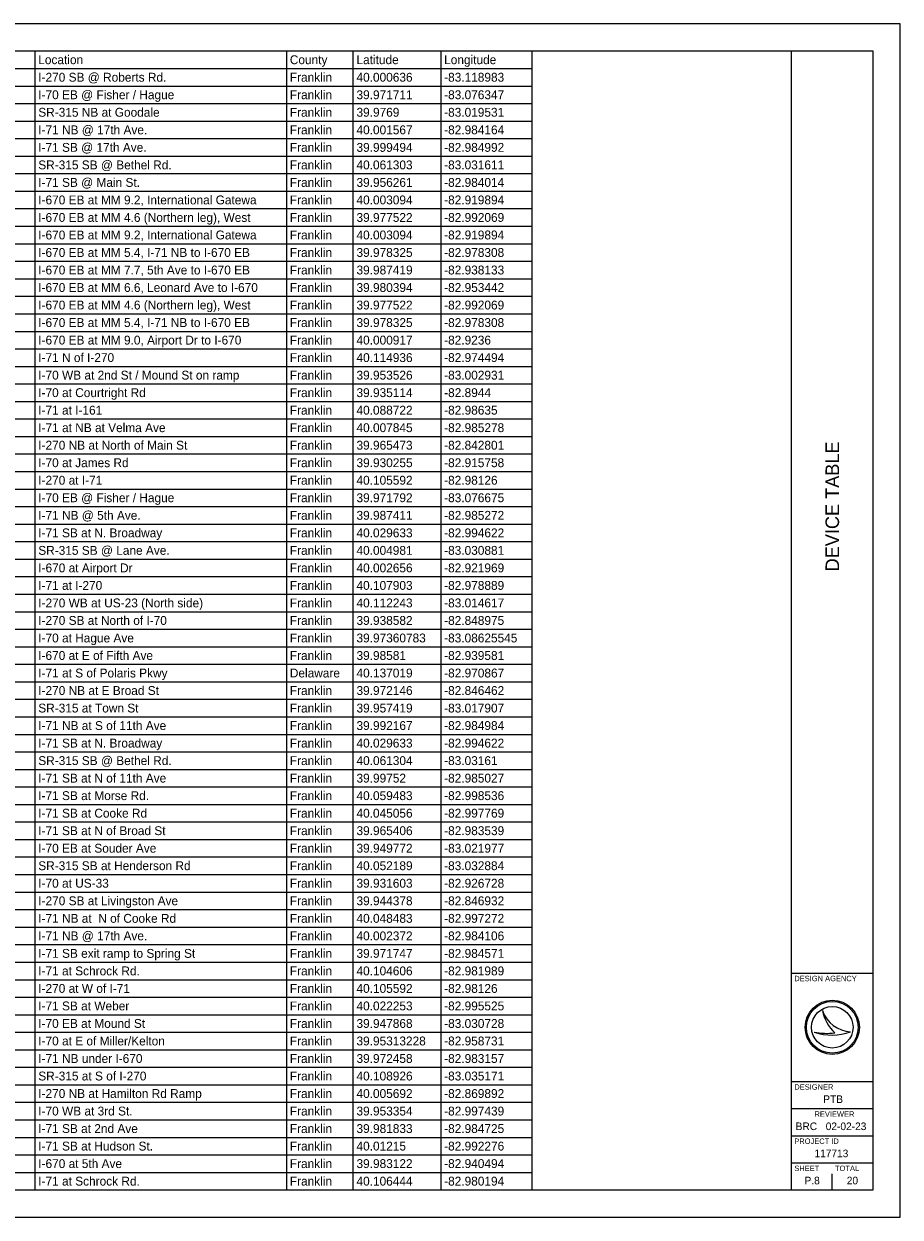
# Model space of a CAD drawing. Extents: x 0 to 34, y 0 to 22.
# Drawn here: x 17.86 to 34, y 0 to 22 of the extents above; entities that cross this region are included whole.
import ezdxf

# ---------------------------------------------------------------- set-up
doc = ezdxf.new("R2010")
doc.units = 0
for name, color, linetype in [('SH_Border', 7, 'Continuous'), ('SH_Cut_Line', 7, 'Continuous'), ('SH_Data', 7, 'Continuous'), ('SH_Text', 7, 'Continuous')]:
    doc.layers.add(name, color=color, linetype=linetype)

msp = doc.modelspace()

# ---------------------------------------------------------------- linework, layer by layer
at = {"layer": 'SH_Border'}
for p, q in [((32, 0.5), (32, 21.5)), ((32, 4.5), (33.5, 4.5)), ((32, 2.5), (33.5, 2.5)), ((32, 2), (33.5, 2)), ((32, 1.5), (33.5, 1.5)), ((32, 1), (33.5, 1))]:
    msp.add_line(p, q, dxfattribs=at)
msp.add_lwpolyline([(1.5, 21.5), (33.5, 21.5), (33.5, 0.5), (1.5, 0.5)], close=True, dxfattribs=at)
at = {"layer": 'SH_Cut_Line'}
msp.add_lwpolyline([(0, 0), (34, 0), (34, 22), (0, 22)], close=True, dxfattribs=at)
at = {"layer": 'SH_Data'}
for p, q in [((32.567, 3.81), (32.567, 3.81)), ((32.417, 3.41), (32.417, 3.41)), ((32.75, 3.5), (32.75, 3.5)), ((33.087, 3.419), (33.087, 3.419)), ((32.375, 0.675), (32.375, 0.675)), ((32.75, 0.5), (32.75, 0.8))]:
    msp.add_line(p, q, dxfattribs=at)
for radius in [0.5, 0.477, 0.477, 0.382]:
    msp.add_circle((32.75, 3.5), radius, dxfattribs=at)
for centre, radius, start, end in [((33.116, 3.998), 0.58, 198.9257, 198.9319), ((33.347, 3.97), 0.796, 191.6379, 191.6421), ((33.116, 3.998), 0.58, 198.9319, 267.1657), ((33.347, 3.97), 0.796, 191.6421, 226.0947), ((32.739, 4.37), 1.013, 251.4576, 290.0832), ((32.648, 4.654), 1.266, 259.4964, 259.4995), ((32.739, 4.37), 1.013, 251.4527, 251.4576), ((32.648, 4.654), 1.266, 259.4995, 276.6672)]:
    msp.add_arc(centre, radius, start, end, dxfattribs=at)
at = {"layer": 'SH_Text'}
for p, q in [((1.5, 21.5), (27.214, 21.5)), ((18.056, 21.5), (18.056, 0.502)), ((22.692, 21.5), (22.692, 0.502)), ((23.919, 21.5), (23.919, 0.502)), ((25.535, 21.5), (25.535, 0.502)), ((27.214, 21.5), (27.214, 0.502)), ((1.5, 21.177), (27.214, 21.177)), ((1.5, 20.854), (27.214, 20.854)), ((1.5, 20.531), (27.214, 20.531)), ((1.5, 20.208), (27.214, 20.208)), ((1.5, 19.885), (27.214, 19.885)), ((1.5, 19.562), (27.214, 19.562)), ((1.5, 19.239), (27.214, 19.239)), ((1.5, 18.916), (27.214, 18.916)), ((1.5, 18.593), (27.214, 18.593)), ((1.5, 18.269), (27.214, 18.269)), ((1.5, 17.946), (27.214, 17.946)), ((1.5, 17.623), (27.214, 17.623)), ((1.5, 17.3), (27.214, 17.3)), ((1.5, 16.977), (27.214, 16.977)), ((1.5, 16.654), (27.214, 16.654)), ((1.5, 16.331), (27.214, 16.331)), ((1.5, 16.008), (27.214, 16.008)), ((1.5, 15.685), (27.214, 15.685)), ((1.5, 15.362), (27.214, 15.362)), ((1.5, 15.039), (27.214, 15.039)), ((1.5, 14.716), (27.214, 14.716)), ((1.5, 14.393), (27.214, 14.393)), ((1.5, 14.07), (27.214, 14.07)), ((1.5, 13.747), (27.214, 13.747)), ((1.5, 13.424), (27.214, 13.424)), ((1.5, 13.101), (27.214, 13.101)), ((1.5, 12.778), (27.214, 12.778)), ((1.5, 12.455), (27.214, 12.455)), ((1.5, 12.132), (27.214, 12.132)), ((1.5, 11.809), (27.214, 11.809)), ((1.5, 11.486), (27.214, 11.486)), ((1.5, 11.162), (27.214, 11.162)), ((1.5, 10.839), (27.214, 10.839)), ((1.5, 10.516), (27.214, 10.516)), ((1.5, 10.193), (27.214, 10.193)), ((1.5, 9.87), (27.214, 9.87)), ((1.5, 9.547), (27.214, 9.547)), ((1.5, 9.224), (27.214, 9.224)), ((1.5, 8.901), (27.214, 8.901)), ((1.5, 8.578), (27.214, 8.578)), ((1.5, 8.255), (27.214, 8.255)), ((1.5, 7.932), (27.214, 7.932)), ((1.5, 7.609), (27.214, 7.609)), ((1.5, 7.286), (27.214, 7.286)), ((1.5, 6.963), (27.214, 6.963)), ((1.5, 6.64), (27.214, 6.64)), ((1.5, 6.317), (27.214, 6.317)), ((1.5, 5.994), (27.214, 5.994)), ((1.5, 5.671), (27.214, 5.671)), ((1.5, 5.348), (27.214, 5.348)), ((1.5, 5.025), (27.214, 5.025)), ((1.5, 4.702), (27.214, 4.702)), ((1.5, 4.378), (27.214, 4.378)), ((1.5, 4.055), (27.214, 4.055)), ((1.5, 3.732), (27.214, 3.732)), ((1.5, 3.409), (27.214, 3.409)), ((1.5, 3.086), (27.214, 3.086)), ((1.5, 2.763), (27.214, 2.763)), ((1.5, 2.44), (27.214, 2.44)), ((1.5, 2.117), (27.214, 2.117)), ((1.5, 1.794), (27.214, 1.794)), ((1.5, 1.471), (27.214, 1.471)), ((1.5, 1.148), (27.214, 1.148)), ((1.5, 0.825), (27.214, 0.825)), ((1.5, 0.502), (27.214, 0.502))]:
    msp.add_line(p, q, dxfattribs=at)

# ---------------------------------------------------------------- texts
at = {"layer": 'SH_Data'}
msp.add_text('DEVICE TABLE', height=0.25, rotation=90, dxfattribs=at).set_placement((32.875, 11.905))
for s, height, p in [('DESIGN AGENCY', 0.1, (32.05, 4.35)), ('DESIGNER', 0.1, (32.05, 2.35)), ('PTB', 0.14, (32.584, 2.105)), ('REVIEWER', 0.1, (32.422, 1.85)), ('BRC', 0.14, (32.075, 1.605)), ('02-02-23', 0.14, (32.629, 1.605)), ('PROJECT ID', 0.1, (32.05, 1.35)), ('117713', 0.14, (32.421, 1.105)), ('SHEET', 0.1, (32.05, 0.85)), ('TOTAL', 0.1, (32.8, 0.85)), ('P.8', 0.14, (32.239, 0.605)), ('20', 0.14, (33.017, 0.605))]:
    msp.add_text(s, height=height, dxfattribs=at).set_placement(p)
at = {"layer": 'SH_Text'}
for s, height, p in [('Location', 0.1635, (18.121, 21.257)), ('County', 0.1635, (22.756, 21.257)), ('Latitude', 0.1635, (23.984, 21.257)), ('Longitude', 0.1635, (25.599, 21.257)), ('I-270 SB @ Roberts Rd.', 0.16346, (18.121, 20.934)), ('Franklin', 0.1635, (22.756, 20.934)), ('40.000636', 0.1635, (23.984, 20.934)), ('-83.118983', 0.1635, (25.599, 20.934)), ('I-70 EB @ Fisher / Hague', 0.16346, (18.121, 20.611)), ('Franklin', 0.1635, (22.756, 20.611)), ('39.971711', 0.1635, (23.984, 20.611)), ('-83.076347', 0.1635, (25.599, 20.611)), ('SR-315 NB at Goodale', 0.16346, (18.121, 20.288)), ('Franklin', 0.1635, (22.756, 20.288)), ('39.9769', 0.1635, (23.984, 20.288)), ('-83.019531', 0.1635, (25.599, 20.288)), ('I-71 NB @ 17th Ave.', 0.16346, (18.121, 19.964)), ('Franklin', 0.1635, (22.756, 19.964)), ('40.001567', 0.1635, (23.984, 19.964)), ('-82.984164', 0.1635, (25.599, 19.964)), ('I-71 SB @ 17th Ave.', 0.16346, (18.121, 19.641)), ('Franklin', 0.1635, (22.756, 19.641)), ('39.999494', 0.1635, (23.984, 19.641)), ('-82.984992', 0.1635, (25.599, 19.641)), ('SR-315 SB @ Bethel Rd.', 0.16346, (18.121, 19.318)), ('Franklin', 0.1635, (22.756, 19.318)), ('40.061303', 0.1635, (23.984, 19.318)), ('-83.031611', 0.1635, (25.599, 19.318)), ('I-71 SB @ Main St.', 0.16346, (18.121, 18.995)), ('Franklin', 0.1635, (22.756, 18.995)), ('39.956261', 0.1635, (23.984, 18.995)), ('-82.984014', 0.1635, (25.599, 18.995)), ('I-670 EB at MM 9.2, International Gatewa', 0.16346, (18.121, 18.672)), ('Franklin', 0.1635, (22.756, 18.672)), ('40.003094', 0.1635, (23.984, 18.672)), ('-82.919894', 0.1635, (25.599, 18.672)), ('I-670 EB at MM 4.6 (Northern leg), West', 0.16346, (18.121, 18.349)), ('Franklin', 0.1635, (22.756, 18.349)), ('39.977522', 0.1635, (23.984, 18.349)), ('-82.992069', 0.1635, (25.599, 18.349)), ('I-670 EB at MM 9.2, International Gatewa', 0.16346, (18.121, 18.026)), ('Franklin', 0.1635, (22.756, 18.026)), ('40.003094', 0.1635, (23.984, 18.026)), ('-82.919894', 0.1635, (25.599, 18.026)), ('I-670 EB at MM 5.4, I-71 NB to I-670 EB', 0.16346, (18.121, 17.703)), ('Franklin', 0.1635, (22.756, 17.703)), ('39.978325', 0.1635, (23.984, 17.703)), ('-82.978308', 0.1635, (25.599, 17.703)), ('I-670 EB at MM 7.7, 5th Ave to I-670 EB', 0.16346, (18.121, 17.38)), ('Franklin', 0.1635, (22.756, 17.38)), ('39.987419', 0.1635, (23.984, 17.38)), ('-82.938133', 0.1635, (25.599, 17.38)), ('I-670 EB at MM 6.6, Leonard Ave to I-670', 0.16346, (18.121, 17.057)), ('Franklin', 0.1635, (22.756, 17.057)), ('39.980394', 0.1635, (23.984, 17.057)), ('-82.953442', 0.1635, (25.599, 17.057)), ('I-670 EB at MM 4.6 (Northern leg), West', 0.16346, (18.121, 16.734)), ('Franklin', 0.1635, (22.756, 16.734)), ('39.977522', 0.1635, (23.984, 16.734)), ('-82.992069', 0.1635, (25.599, 16.734)), ('I-670 EB at MM 5.4, I-71 NB to I-670 EB', 0.16346, (18.121, 16.411)), ('Franklin', 0.1635, (22.756, 16.411)), ('39.978325', 0.1635, (23.984, 16.411)), ('-82.978308', 0.1635, (25.599, 16.411)), ('I-670 EB at MM 9.0, Airport Dr to I-670', 0.16346, (18.121, 16.088)), ('Franklin', 0.1635, (22.756, 16.088)), ('40.000917', 0.1635, (23.984, 16.088)), ('-82.9236', 0.1635, (25.599, 16.088)), ('I-71 N of I-270', 0.16346, (18.121, 15.765)), ('Franklin', 0.1635, (22.756, 15.765)), ('40.114936', 0.1635, (23.984, 15.765)), ('-82.974494', 0.1635, (25.599, 15.765)), ('I-70 WB at 2nd St / Mound St on ramp', 0.16346, (18.121, 15.442)), ('Franklin', 0.1635, (22.756, 15.442)), ('39.953526', 0.1635, (23.984, 15.442)), ('-83.002931', 0.1635, (25.599, 15.442)), ('I-70 at Courtright Rd', 0.16346, (18.121, 15.119)), ('Franklin', 0.1635, (22.756, 15.119)), ('39.935114', 0.1635, (23.984, 15.119)), ('-82.8944', 0.1635, (25.599, 15.119)), ('I-71 at I-161', 0.16346, (18.121, 14.796)), ('Franklin', 0.1635, (22.756, 14.796)), ('40.088722', 0.1635, (23.984, 14.796)), ('-82.98635', 0.1635, (25.599, 14.796)), ('I-71 at NB at Velma Ave', 0.16346, (18.121, 14.473)), ('Franklin', 0.1635, (22.756, 14.473)), ('40.007845', 0.1635, (23.984, 14.473)), ('-82.985278', 0.1635, (25.599, 14.473)), ('I-270 NB at North of Main St', 0.16346, (18.121, 14.15)), ('Franklin', 0.1635, (22.756, 14.15)), ('39.965473', 0.1635, (23.984, 14.15)), ('-82.842801', 0.1635, (25.599, 14.15)), ('I-70 at James Rd', 0.16346, (18.121, 13.827)), ('Franklin', 0.1635, (22.756, 13.827)), ('39.930255', 0.1635, (23.984, 13.827)), ('-82.915758', 0.1635, (25.599, 13.827)), ('I-270 at I-71', 0.16346, (18.121, 13.504)), ('Franklin', 0.1635, (22.756, 13.504)), ('40.105592', 0.1635, (23.984, 13.504)), ('-82.98126', 0.1635, (25.599, 13.504)), ('I-70 EB @ Fisher / Hague', 0.16346, (18.121, 13.181)), ('Franklin', 0.1635, (22.756, 13.181)), ('39.971792', 0.1635, (23.984, 13.181)), ('-83.076675', 0.1635, (25.599, 13.181)), ('I-71 NB @ 5th Ave.', 0.16346, (18.121, 12.857)), ('Franklin', 0.1635, (22.756, 12.857)), ('39.987411', 0.1635, (23.984, 12.857)), ('-82.985272', 0.1635, (25.599, 12.857)), ('I-71 SB at N. Broadway', 0.16346, (18.121, 12.534)), ('Franklin', 0.1635, (22.756, 12.534)), ('40.029633', 0.1635, (23.984, 12.534)), ('-82.994622', 0.1635, (25.599, 12.534)), ('SR-315 SB @ Lane Ave.', 0.16346, (18.121, 12.211)), ('Franklin', 0.1635, (22.756, 12.211)), ('40.004981', 0.1635, (23.984, 12.211)), ('-83.030881', 0.1635, (25.599, 12.211)), ('I-670 at Airport Dr', 0.16346, (18.121, 11.888)), ('Franklin', 0.1635, (22.756, 11.888)), ('40.002656', 0.1635, (23.984, 11.888)), ('-82.921969', 0.1635, (25.599, 11.888)), ('I-71 at I-270', 0.16346, (18.121, 11.565)), ('Franklin', 0.1635, (22.756, 11.565)), ('40.107903', 0.1635, (23.984, 11.565)), ('-82.978889', 0.1635, (25.599, 11.565)), ('I-270 WB at US-23 (North side)', 0.16346, (18.121, 11.242)), ('Franklin', 0.1635, (22.756, 11.242)), ('40.112243', 0.1635, (23.984, 11.242)), ('-83.014617', 0.1635, (25.599, 11.242)), ('I-270 SB at North of I-70', 0.16346, (18.121, 10.919)), ('Franklin', 0.1635, (22.756, 10.919)), ('39.938582', 0.1635, (23.984, 10.919)), ('-82.848975', 0.1635, (25.599, 10.919)), ('I-70 at Hague Ave', 0.16346, (18.121, 10.596)), ('Franklin', 0.1635, (22.756, 10.596)), ('39.97360783', 0.16346, (23.984, 10.596)), ('-83.08625545', 0.16346, (25.599, 10.596)), ('I-670 at E of Fifth Ave', 0.16346, (18.121, 10.273)), ('Franklin', 0.1635, (22.756, 10.273)), ('39.98581', 0.1635, (23.984, 10.273)), ('-82.939581', 0.1635, (25.599, 10.273)), ('I-71 at S of Polaris Pkwy', 0.16346, (18.121, 9.95)), ('Delaware', 0.1635, (22.756, 9.95)), ('40.137019', 0.1635, (23.984, 9.95)), ('-82.970867', 0.1635, (25.599, 9.95)), ('I-270 NB at E Broad St', 0.16346, (18.121, 9.627)), ('Franklin', 0.1635, (22.756, 9.627)), ('39.972146', 0.1635, (23.984, 9.627)), ('-82.846462', 0.1635, (25.599, 9.627)), ('SR-315 at Town St', 0.16346, (18.121, 9.304)), ('Franklin', 0.1635, (22.756, 9.304)), ('39.957419', 0.1635, (23.984, 9.304)), ('-83.017907', 0.1635, (25.599, 9.304)), ('I-71 NB at S of 11th Ave', 0.16346, (18.121, 8.981)), ('Franklin', 0.1635, (22.756, 8.981)), ('39.992167', 0.1635, (23.984, 8.981)), ('-82.984984', 0.1635, (25.599, 8.981)), ('I-71 SB at N. Broadway', 0.16346, (18.121, 8.658)), ('Franklin', 0.1635, (22.756, 8.658)), ('40.029633', 0.1635, (23.984, 8.658)), ('-82.994622', 0.1635, (25.599, 8.658)), ('SR-315 SB @ Bethel Rd.', 0.16346, (18.121, 8.335)), ('Franklin', 0.1635, (22.756, 8.335)), ('40.061304', 0.1635, (23.984, 8.335)), ('-83.03161', 0.1635, (25.599, 8.335)), ('I-71 SB at N of 11th Ave', 0.16346, (18.121, 8.012)), ('Franklin', 0.1635, (22.756, 8.012)), ('39.99752', 0.1635, (23.984, 8.012)), ('-82.985027', 0.1635, (25.599, 8.012)), ('I-71 SB at Morse Rd.', 0.16346, (18.121, 7.689)), ('Franklin', 0.1635, (22.756, 7.689)), ('40.059483', 0.1635, (23.984, 7.689)), ('-82.998536', 0.1635, (25.599, 7.689)), ('I-71 SB at Cooke Rd', 0.16346, (18.121, 7.366)), ('Franklin', 0.1635, (22.756, 7.366)), ('40.045056', 0.1635, (23.984, 7.366)), ('-82.997769', 0.1635, (25.599, 7.366)), ('I-71 SB at N of Broad St', 0.16346, (18.121, 7.043)), ('Franklin', 0.1635, (22.756, 7.043)), ('39.965406', 0.1635, (23.984, 7.043)), ('-82.983539', 0.1635, (25.599, 7.043)), ('I-70 EB at Souder Ave', 0.16346, (18.121, 6.72)), ('Franklin', 0.1635, (22.756, 6.72)), ('39.949772', 0.1635, (23.984, 6.72)), ('-83.021977', 0.1635, (25.599, 6.72)), ('SR-315 SB at Henderson Rd', 0.16346, (18.121, 6.397)), ('Franklin', 0.1635, (22.756, 6.397)), ('40.052189', 0.1635, (23.984, 6.397)), ('-83.032884', 0.1635, (25.599, 6.397)), ('I-70 at US-33', 0.16346, (18.121, 6.074)), ('Franklin', 0.1635, (22.756, 6.074)), ('39.931603', 0.1635, (23.984, 6.074)), ('-82.926728', 0.1635, (25.599, 6.074)), ('I-270 SB at Livingston Ave', 0.16346, (18.121, 5.75)), ('Franklin', 0.1635, (22.756, 5.75)), ('39.944378', 0.1635, (23.984, 5.75)), ('-82.846932', 0.1635, (25.599, 5.75)), ('I-71 NB at  N of Cooke Rd', 0.16346, (18.121, 5.427)), ('Franklin', 0.1635, (22.756, 5.427)), ('40.048483', 0.1635, (23.984, 5.427)), ('-82.997272', 0.1635, (25.599, 5.427)), ('I-71 NB @ 17th Ave.', 0.16346, (18.121, 5.104)), ('Franklin', 0.1635, (22.756, 5.104)), ('40.002372', 0.1635, (23.984, 5.104)), ('-82.984106', 0.1635, (25.599, 5.104)), ('I-71 SB exit ramp to Spring St', 0.16346, (18.121, 4.781)), ('Franklin', 0.1635, (22.756, 4.781)), ('39.971747', 0.1635, (23.984, 4.781)), ('-82.984571', 0.1635, (25.599, 4.781)), ('I-71 at Schrock Rd.', 0.16346, (18.121, 4.458)), ('Franklin', 0.1635, (22.756, 4.458)), ('40.104606', 0.1635, (23.984, 4.458)), ('-82.981989', 0.1635, (25.599, 4.458)), ('I-270 at W of I-71', 0.16346, (18.121, 4.135)), ('Franklin', 0.1635, (22.756, 4.135)), ('40.105592', 0.1635, (23.984, 4.135)), ('-82.98126', 0.1635, (25.599, 4.135)), ('I-71 SB at Weber', 0.16346, (18.121, 3.812)), ('Franklin', 0.1635, (22.756, 3.812)), ('40.022253', 0.1635, (23.984, 3.812)), ('-82.995525', 0.1635, (25.599, 3.812)), ('I-70 EB at Mound St', 0.16346, (18.121, 3.489)), ('Franklin', 0.1635, (22.756, 3.489)), ('39.947868', 0.1635, (23.984, 3.489)), ('-83.030728', 0.1635, (25.599, 3.489)), ('I-70 at E of Miller/Kelton', 0.16346, (18.121, 3.166)), ('Franklin', 0.1635, (22.756, 3.166)), ('39.95313228', 0.16346, (23.984, 3.166)), ('-82.958731', 0.1635, (25.599, 3.166)), ('I-71 NB under I-670', 0.16346, (18.121, 2.843)), ('Franklin', 0.1635, (22.756, 2.843)), ('39.972458', 0.1635, (23.984, 2.843)), ('-82.983157', 0.1635, (25.599, 2.843)), ('SR-315 at S of I-270', 0.16346, (18.121, 2.52)), ('Franklin', 0.1635, (22.756, 2.52)), ('40.108926', 0.1635, (23.984, 2.52)), ('-83.035171', 0.1635, (25.599, 2.52)), ('I-270 NB at Hamilton Rd Ramp', 0.16346, (18.121, 2.197)), ('Franklin', 0.1635, (22.756, 2.197)), ('40.005692', 0.1635, (23.984, 2.197)), ('-82.869892', 0.1635, (25.599, 2.197)), ('I-70 WB at 3rd St.', 0.16346, (18.121, 1.874)), ('Franklin', 0.1635, (22.756, 1.874)), ('39.953354', 0.1635, (23.984, 1.874)), ('-82.997439', 0.1635, (25.599, 1.874)), ('I-71 SB at 2nd Ave', 0.16346, (18.121, 1.551)), ('Franklin', 0.1635, (22.756, 1.551)), ('39.981833', 0.1635, (23.984, 1.551)), ('-82.984725', 0.1635, (25.599, 1.551)), ('I-71 SB at Hudson St.', 0.16346, (18.121, 1.228)), ('Franklin', 0.1635, (22.756, 1.228)), ('40.01215', 0.1635, (23.984, 1.228)), ('-82.992276', 0.1635, (25.599, 1.228)), ('I-670 at 5th Ave', 0.16346, (18.121, 0.905)), ('Franklin', 0.1635, (22.756, 0.905)), ('39.983122', 0.1635, (23.984, 0.905)), ('-82.940494', 0.1635, (25.599, 0.905)), ('I-71 at Schrock Rd.', 0.16346, (18.121, 0.582)), ('Franklin', 0.1635, (22.756, 0.582)), ('40.106444', 0.1635, (23.984, 0.582)), ('-82.980194', 0.1635, (25.599, 0.582))]:
    msp.add_text(s, height=height, dxfattribs=at).set_placement(p)

doc.saveas('drawing.dxf')
